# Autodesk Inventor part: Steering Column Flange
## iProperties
Shininess: 64.0
Length Units: 11269
Angle Units: 11279
Time Units: 11290
Mass Units: 11283
Length Display Precision: 3
Angle Display Precision: 2
Compacted: True
Part Number: Steering Column Flange
Document SubType Name: Modeling
Created: 2004-03
Designer: rak
Manufacturer: Standard
Standards Organization: Custom
Density: 0.0
Volumn: 0.0
Area: 0.0
PropertySet Name: Model Information
Control State: 0
Master: False
Checked Out: False
Author: rak
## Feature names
1. Extrusion1
